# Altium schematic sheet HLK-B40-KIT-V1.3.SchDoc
size A3
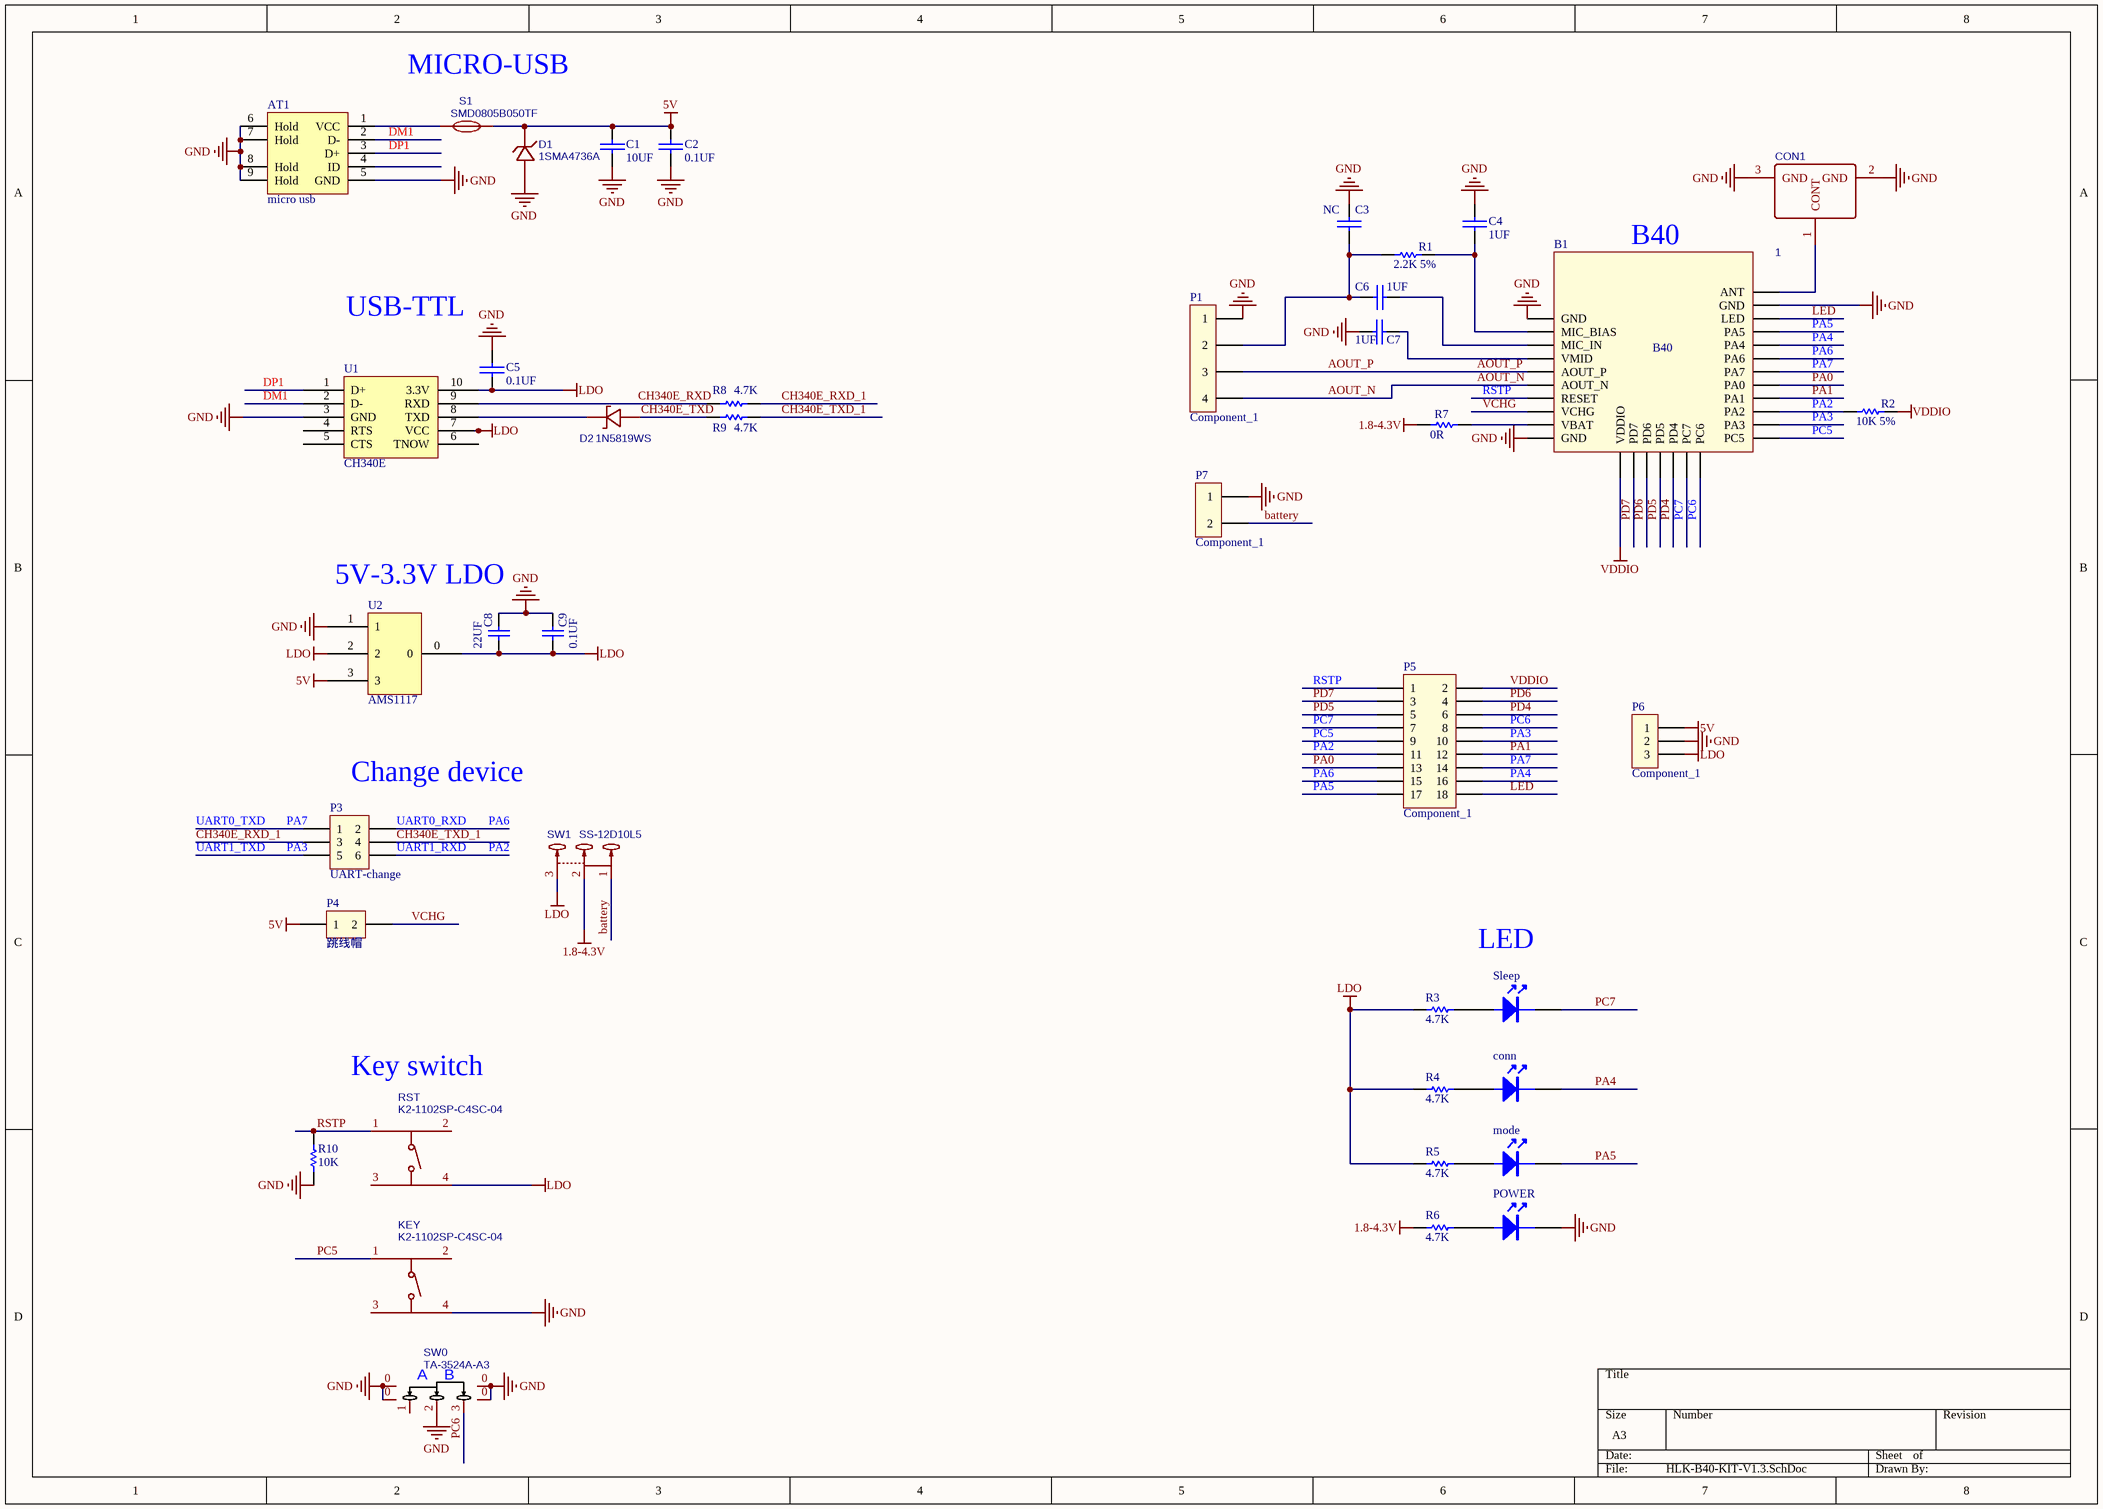
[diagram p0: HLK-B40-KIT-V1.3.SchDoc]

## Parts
AT1  micro usb  [USB-MICRO_D]
B1  B40  [B40]
C1  10UF  [0603]
C2  0.1UF  [0603]
C3  NC  [0402]
C4  1UF  [0402]
C5  0.1UF  [0603]
C6  1UF  [0402]
C7  1UF  [0402]
C8  22UF  [0603]
C9  0.1UF  [0603]
CON1  1  [SMA/UFLR/NI]
conn  (no value)  [0603LED]
D1  1SMA4736A  [SMA_L4.4-W2.8-LS5.4-RD]
D2  1N5819WS  [SOD-323_L1.8-W1.3-LS2.5-RD]
KEY  K2-1102SP-C4SC-04  [KEY-SMD_4P-L6.0-W6.0-P4.50-LS9.5]
mode  (no value)  [0603LED]
P1  Component_1  [2.54*4]
P3  UART-change  [2.54*2*3]
P4  跳线帽  [2.54*2]
P5  Component_1  [2.54*18]
P6  Component_1  [2.54*3]
P7  Component_1  [2.54*2]
POWER  (no value)  [0603LED]
R1  2.2K 5%  [0402]
R2  10K 5%  [0603]
R3  4.7K  [0603]
R4  4.7K  [0603]
R5  4.7K  [0603]
R6  4.7K  [0603]
R7  0R  [R0805]
R8  4.7K  [0603]
R9  4.7K  [0603]
R10  10K  [0603]
RST  K2-1102SP-C4SC-04  [KEY-SMD_4P-L6.0-W6.0-P4.50-LS9.5]
S1  SMD0805B050TF  [R0805]
Sleep  (no value)  [0603LED]
SW0  TA-3524A-A3  [SW-SMD_3P-L6.6-W2.7-P1.50]
SW1  SS-12D10L5  [SW-TH_SS-12D10L5]
U1  CH340E  [MSOP-10]
U2  AMS1117  [1117]

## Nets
1.8-4.3V: R6.1 R7.1 SW1.2
5V: C1.2 C2.2 D1.1 P4.1 P6.1 S1.2 U2.3
GND: AT1.5(GND) AT1.6(Hold) AT1.7(Hold) AT1.8(Hold) AT1.9(Hold) B1.1(GND) B1.10(GND) B1.28(GND) C1.1 C2.1 C3.2 C4.2 C5.1 C7.2 C8.1 C9.1 CON1.2(GND) CON1.3(GND) D1.2 KEY.4 P1.1 P6.2 P7.1 POWER.2 R10.1 SW0.0 SW0.2 U1.3(GND) U2.1
LDO: C5.2 C8.2 C9.2 P6.3 R3.1 R4.1 R5.1 RST.4 SW1.3 U1.7(VCC) U1.10(3.3V) U2.0 U2.2
VDDIO: B1.11(VDDIO) P5.2 R2.1
AOUT_N: B1.6(AOUT_N) P1.4
AOUT_P: B1.5(AOUT_P) P1.3
battery: P7.2 SW1.1
CH340E_RXD: R8.1 U1.9(RXD)
CH340E_RXD_1: P3.3 R8.2
CH340E_TXD: D2.2(A) R9.1
CH340E_TXD_1: P3.4 R9.2
DM1: AT1.2(D-) U1.2(D-)
DP1: AT1.3(D+) U1.1(D+)
LED: B1.27(LED) P5.18
PA0: B1.22(PA0) P5.13
PA1: B1.21(PA1) P5.12
PA2: B1.20(PA2) P3.6 P5.11 R2.2  [also labelled UART1_RXD]
PA3: B1.19(PA3) P3.5 P5.10  [also labelled UART1_TXD]
PA4: B1.25(PA4) conn.2 P5.16
PA5: B1.26(PA5) mode.2 P5.17
PA6: B1.24(PA6) P3.2 P5.15  [also labelled UART0_RXD]
PA7: B1.23(PA7) P3.1 P5.14  [also labelled UART0_TXD]
PC5: B1.18(PC5) KEY.1 P5.9
PC6: B1.17(PC6) P5.8 SW0.3
PC7: B1.16(PC7) P5.7 Sleep.2
PD4: B1.15(PD4) P5.6
PD5: B1.14(PD5) P5.5
PD6: B1.13(PD6) P5.4
PD7: B1.12(PD7) P5.3
RSTP: B1.7(RESET) P5.1 R10.2 RST.1
VCHG: B1.8(VCHG) P4.2
NetAT1_1: AT1.1(VCC) S1.1
NetB1_2: B1.2(MIC_BIAS) C4.1 R1.1
NetB1_3: B1.3(MIC_IN) C6.1
NetB1_4: B1.4(VMID) C7.1
NetB1_9: B1.9(VBAT) R7.2
NetB1_29: B1.29(ANT) CON1.1(CONT)
NetC3_1: C3.1 C6.2 P1.2 R1.2
Netconn_1: conn.1 R4.2
NetD2_1: D2.1(C) U1.8(TXD)
Netmode_1: mode.1 R5.2
NetPOWER_1: POWER.1 R6.2
NetR3_2: R3.2 Sleep.1

Not connected (* = marked no-connect by the designer): AT1 4(ID); KEY 2 3; RST 2 3; SW0 1; U1 4(RTS) 5(CTS) 6(TNOW)

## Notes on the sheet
- MICRO-USB
- (near B1) B40
- USB-TTL
- 5V-3.3V LDO
- (near P3) Change device
- LED
- Key switch

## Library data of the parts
AT1 = USB-D
C1-C7 = CAP: Capacitor
C8 C9 = Cap: Capacitor; Value: 100pF
CON1 = KH-IPEX-K501-29: BOM_Manufacturer: Shenzhen Kinghelm Elec; Contributor: LCSC
conn mode POWER Sleep = LED
D1 = 1SMA4736A: BOM_Manufacturer: LGE; Contributor: LCSC
D2 = 1N5819WS: BOM_Manufacturer: Guangdong Hottech; Contributor: LCSC; SMT Type: Extend
KEY RST = K2-1102SP-C4SC-04: BOM_Manufacturer: HRO; Contributor: LCSC
P1 P7 = Component_1_1
P3 P4 U2 = Component_1
R1-R10 = Res1: Resistor
S1 = SMD0805B050TF: BOM_Manufacturer: Brightking Elec (TAIWAN); Contributor: LCSC
SW0 = TA-3524A-A3: BOM_Manufacturer: Yuandi; Contributor: LCSC
SW1 = SS-12D10L5: BOM_Manufacturer: XKB Enterprise; Contributor: LCSC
